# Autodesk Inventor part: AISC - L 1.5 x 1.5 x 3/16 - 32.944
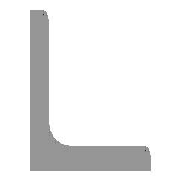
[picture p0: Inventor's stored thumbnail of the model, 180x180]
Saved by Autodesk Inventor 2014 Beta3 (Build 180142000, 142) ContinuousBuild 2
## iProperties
Created: 2010-11
Part Number: AISC - L 1.5 x 1.5 x 3/16 - 32.944
Material: Steel, Mild
Description: Angle Steel
Document SubType Name: Modeling
Standard: ANSI
Designer: Beta-8540w
Standards Organization: ANSI
Language: en-US
Size Designation: L 1.5 x 1.5 x 3/16
Categories: <MemberInstance><Categories><Category DisplayName="Structural Shapes" InternalName="089c4875-fa83-4c05-b084-43b9cc11f5ed" Mnemonic="GRDR"><CategoryParameter Dis
Stock Number: L 1.5 x 1.5 x 3/16
Density: 7.86 g/cm^3
Appearance: Steel
IsCustomPart: 1
_CCFamilyMember: 5
_CCFamilyDisplayName: ANSI L (Equal angles) - Angle Steel
_FrameMemberDoc: Frame Member File
_Version: 15.0.0
_GetPNFromCC: 1
G_L: 32.944 in
G_W: 1.500 in
G_H: 1.500 in
Author: Beta-8540w
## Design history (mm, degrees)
node "Start plane"
node "End plane"
sketch "Sketch"
  geometry: L1 (38.1, 0)-(0, 0); L2 (0, 0)-(0, 38.1); L3 (0, 38.1)-(2.476, 38.1); L4 (4.762, 35.814)-(4.762, 9.589); L5 (9.588, 4.763)-(35.814, 4.763); L6 (38.1, 2.477)-(38.1, 0); L7 (0, -11.041)-(0, 31.538); L8 (-11.041, 0)-(31.538, 0); L9 (0, 48.496)-(0, -20.964) reference; L10 (-20.964, 0)-(48.496, 0) reference; A1 r 4.826 centre (9.588, 9.589) between (4.762, 9.589) and (9.588, 4.763); A2 r 2.286 centre (2.476, 35.814) between (4.762, 35.814) and (2.476, 38.1); A3 r 2.286 centre (35.814, 2.477) between (38.1, 2.477) and (35.814, 4.763); 3 further points
  constraints: 16 end point, 6 point on circle, 6 point on line, 6 tangent, 4 parallel, 3 centre point, 2 collinear, 1 equal radius, 1 horizontal, 1 perpendicular
  dimensions: "d0" = 38.1 distance between parallel lines of L6 L2 (= G_H); "d1" = 38.1 distance between parallel lines of L3 L1 (= G_H); "d2" = 4.7625 distance between parallel lines of L2 L4 (= G_T); "d3" = 4.7625 distance between parallel lines of L1 L5 (= G_T); "d10" = 0 distance between parallel lines of L7 L2 (computed from ex); "d11" = 0 distance between parallel lines of L8 L1 (computed from d10); "d14" = 4.826 radius of A1 (= G_IR); "d15" = 2.286 radius of A2 (= G_ER)
extrude "Body" new body sketch "Sketch" stored distance "d4" = 836.76542 (= G_L); taper "d5" = 0 deg
node "Driven Length"
  sketch "Sketch3"
    geometry: L1 (0, 0)-(10, 0) reference
    constraints: 2 end point, 1 horizontal
  workplane "Work Plane3"
  sketch "Sketch4"
    geometry: L1 (-2, 0)-(12, 0) reference; L2 (-2, 836.765)-(12, 836.765) reference
    dimensions: "d17" = 836.76542 distance between parallel lines of L1 L2 (derived)
body "Solid1"
other parameters: "G_H" = 38.1 [user parameter; used in 2 equation terms], "G_T" = 4.7625 [user parameter; used in 2 equation terms], "G_ER" = 2.286 [user parameter; used in 1 equation term], "G_IR" = 4.826 [user parameter; used in 1 equation term], "G_L" = 836.76542 (= d17) [user parameter; used in 1 equation term], "ex" = 0 [user parameter; used in 1 equation term], "G_OFFSET_START" = 0 [user parameter; used in 1 equation term], "G_OFFSET_END" = 0 [user parameter; used in 1 equation term], "d12" = 0 (computed from G_OFFSET_START), "d13" = 836.76542 (= G_OFFSET_END + B_L), "B_L" = 836.76542 [user parameter; used in 1 equation term], "d16" = 90 deg, "MAS" = 0.26787 [user parameter]
